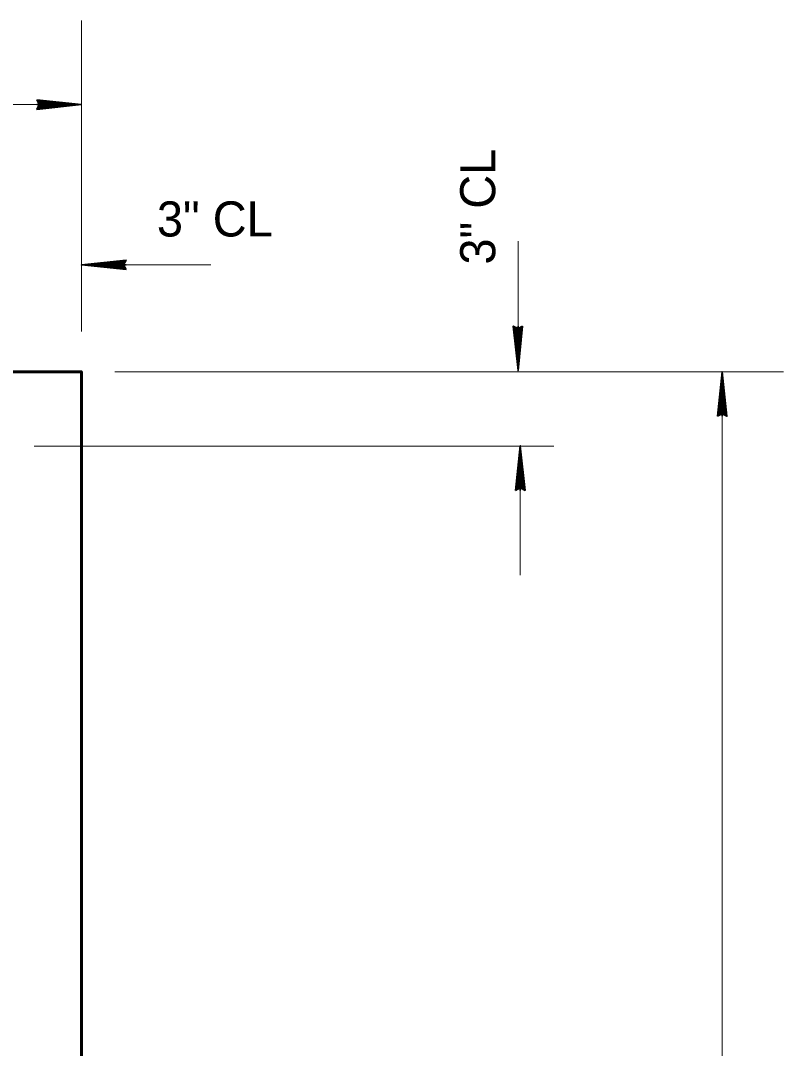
# Model space of a CAD drawing. Extents: x 4.49 to 7.69, y 0.28 to 2.27.
# Drawn here: x 6.09 to 6.2711, y 0.8575 to 1.1015 of the extents above; entities that cross this region are included whole.
import ezdxf

# ---------------------------------------------------------------- set-up
doc = ezdxf.new("R2010")
doc.units = 0
doc.header["$LTSCALE"] = 0.0033
doc.layers.add('1', color=7, linetype='Continuous', lineweight=35)

msp = doc.modelspace()

# ---------------------------------------------------------------- linework, layer by layer
at = {"layer": '1', "lineweight": 13}
for p, q in [((6.104417, 1.027667), (6.104417, 1.1015)), ((5.938, 1.081583), (6.104417, 1.081583)), ((6.208083, 1.028333), (6.208083, 1.049167)), ((6.114333, 1.0435), (6.135167, 1.0435)), ((6.112333, 1.018167), (6.271083, 1.018167)), ((6.2565, 0.602333), (6.2565, 1.018083)), ((6.104417, 0.933083), (6.104417, 1.005917)), ((6.093167, 1.0005), (6.216583, 1.0005)), ((6.208583, 0.969833), (6.208583, 0.990667))]:
    msp.add_line(p, q, dxfattribs=at)
at = {"layer": '1'}
for p, q in [((6.093833, 1.081583), (6.104417, 1.081583)), ((6.094, 1.080917), (6.101333, 1.081667)), ((6.094083, 1.082583), (6.101917, 1.081667)), ((6.094083, 1.082583), (6.101917, 1.081667)), ((6.094083, 1.0825), (6.101917, 1.081667)), ((6.094083, 1.082417), (6.101917, 1.081583)), ((6.094083, 1.082417), (6.101917, 1.081417)), ((6.094083, 1.08075), (6.101417, 1.081583)), ((6.094083, 1.080667), (6.101417, 1.081417)), ((6.094083, 1.0805), (6.101417, 1.081333)), ((6.11475, 1.044583), (6.107417, 1.04375)), ((6.11475, 1.044417), (6.107417, 1.043667)), ((6.11475, 1.044333), (6.107417, 1.0435)), ((6.114833, 1.044167), (6.1075, 1.043417)), ((6.115, 1.0435), (6.104417, 1.0435)), ((6.11475, 1.042667), (6.106917, 1.043667)), ((6.11475, 1.042667), (6.106917, 1.0435)), ((6.11475, 1.0425), (6.106917, 1.043417)), ((6.11475, 1.0425), (6.106917, 1.043417)), ((6.11475, 1.042583), (6.106917, 1.043417)), ((6.207, 1.02875), (6.207833, 1.021417)), ((6.207167, 1.02875), (6.207917, 1.021417)), ((6.20725, 1.02875), (6.208083, 1.021417)), ((6.207417, 1.028833), (6.208167, 1.0215)), ((6.208917, 1.02875), (6.207917, 1.020917)), ((6.208083, 1.029), (6.208083, 1.018417)), ((6.208917, 1.02875), (6.208083, 1.020917)), ((6.209083, 1.02875), (6.208167, 1.020917)), ((6.209083, 1.02875), (6.208167, 1.020917)), ((6.209, 1.02875), (6.208167, 1.020917)), ((6.2565, 1.007583), (6.2565, 1.018167)), ((6.2555, 1.007833), (6.256417, 1.015667)), ((6.2555, 1.007833), (6.256417, 1.015667)), ((6.255583, 1.007833), (6.256417, 1.015667)), ((6.255667, 1.007833), (6.2565, 1.015667)), ((6.255667, 1.007833), (6.256667, 1.015667)), ((6.257167, 1.00775), (6.256417, 1.015083)), ((6.257333, 1.007833), (6.2565, 1.015167)), ((6.257417, 1.007833), (6.256667, 1.015167)), ((6.257583, 1.007833), (6.25675, 1.015167)), ((6.208583, 0.99), (6.208583, 1.000583)), ((6.207583, 0.99025), (6.2085, 0.998083)), ((6.207583, 0.99025), (6.2085, 0.998083)), ((6.207667, 0.99025), (6.2085, 0.998083)), ((6.20775, 0.99025), (6.208583, 0.998083)), ((6.20775, 0.99025), (6.20875, 0.998083)), ((6.20925, 0.990167), (6.2085, 0.9975)), ((6.209417, 0.99025), (6.208583, 0.997583)), ((6.2095, 0.99025), (6.20875, 0.997583)), ((6.209667, 0.99025), (6.208833, 0.997583))]:
    msp.add_line(p, q, dxfattribs=at)
for points in [[(6.093833, 1.082667), (6.104417, 1.081583), (6.093833, 1.080417), (6.094417, 1.081583)], [(6.094583, 1.081667), (6.09925, 1.08175), (6.09925, 1.081667), (6.098333, 1.081667), (6.094583, 1.08175), (6.097583, 1.081833), (6.094417, 1.081917), (6.096667, 1.082), (6.094417, 1.082083), (6.097917, 1.081833), (6.102583, 1.081667), (6.101667, 1.081417), (6.102917, 1.081417), (6.094583, 1.081417), (6.097, 1.08125), (6.094417, 1.08125), (6.09975, 1.081667), (6.094417, 1.081)], [(6.115, 1.042417), (6.104417, 1.0435), (6.115, 1.044667), (6.114417, 1.0435)], [(6.11425, 1.043417), (6.109583, 1.043333), (6.109583, 1.043417), (6.1105, 1.043417), (6.11425, 1.043333), (6.11125, 1.04325), (6.114417, 1.043167), (6.112167, 1.043083), (6.114417, 1.043), (6.110917, 1.04325), (6.10625, 1.043417), (6.107167, 1.043667), (6.105917, 1.043667), (6.11425, 1.043667), (6.111833, 1.043833), (6.114417, 1.043833), (6.109083, 1.043417), (6.114417, 1.044083)], [(6.209167, 1.029), (6.208083, 1.018417), (6.206917, 1.029), (6.208083, 1.028417)], [(6.208167, 1.02825), (6.20825, 1.023583), (6.208167, 1.023583), (6.208167, 1.0245), (6.20825, 1.02825), (6.208333, 1.02525), (6.208417, 1.028417), (6.2085, 1.026167), (6.208583, 1.028417), (6.208333, 1.024917), (6.208167, 1.02025), (6.207917, 1.021167), (6.207917, 1.019917), (6.207917, 1.02825), (6.20775, 1.025833), (6.20775, 1.028417), (6.208167, 1.023083), (6.2075, 1.028417)], [(6.255417, 1.007583), (6.2565, 1.018167), (6.257667, 1.007583), (6.2565, 1.008167)], [(6.256417, 1.008333), (6.256333, 1.013), (6.256417, 1.013), (6.256417, 1.012083), (6.256333, 1.008333), (6.25625, 1.011333), (6.256167, 1.008167), (6.256083, 1.010417), (6.256, 1.008167), (6.25625, 1.011667), (6.256417, 1.016333), (6.256667, 1.015417), (6.256667, 1.016667), (6.256667, 1.008333), (6.256833, 1.01075), (6.256833, 1.008167), (6.256417, 1.0135), (6.257083, 1.008167)], [(6.2075, 0.99), (6.208583, 1.000583), (6.20975, 0.99), (6.208583, 0.990583)], [(6.2085, 0.99075), (6.208417, 0.995417), (6.2085, 0.995417), (6.2085, 0.9945), (6.208417, 0.99075), (6.208333, 0.99375), (6.20825, 0.990583), (6.208167, 0.992833), (6.208083, 0.990583), (6.208333, 0.994083), (6.2085, 0.99875), (6.20875, 0.997833), (6.20875, 0.999083), (6.20875, 0.99075), (6.208917, 0.993167), (6.208917, 0.990583), (6.2085, 0.995917), (6.209167, 0.990583)]]:
    msp.add_lwpolyline(points, close=True, dxfattribs=at)
for points in [[(6.094583, 1.081667), (6.094167, 1.082417), (6.094417, 1.082167), (6.094583, 1.081833), (6.094833, 1.081917), (6.094667, 1.08225), (6.0945, 1.0815), (6.094333, 1.081), (6.094083, 1.080583)], [(6.11425, 1.043417), (6.114667, 1.042667), (6.114417, 1.042917), (6.11425, 1.04325), (6.114, 1.043167), (6.114167, 1.042833), (6.114333, 1.043583), (6.1145, 1.044083), (6.11475, 1.0445)], [(6.208167, 1.02825), (6.208917, 1.028667), (6.208667, 1.028417), (6.208333, 1.02825), (6.208417, 1.028), (6.20875, 1.028167), (6.208, 1.028333), (6.2075, 1.0285), (6.207083, 1.02875)], [(6.256417, 1.008333), (6.255667, 1.007917), (6.255917, 1.008167), (6.25625, 1.008333), (6.256167, 1.008583), (6.255833, 1.008417), (6.256583, 1.00825), (6.257083, 1.008083), (6.2575, 1.007833)], [(6.2085, 0.99075), (6.20775, 0.990333), (6.208, 0.990583), (6.208333, 0.99075), (6.20825, 0.991), (6.207917, 0.990833), (6.208667, 0.990667), (6.209167, 0.9905), (6.209583, 0.99025)]]:
    msp.add_lwpolyline(points, dxfattribs=at)
at = {"layer": '1', "lineweight": 60}
msp.add_lwpolyline([(5.854417, 0.684833), (5.93775, 0.684833), (5.93775, 1.018167), (6.104417, 1.018167), (6.104417, 0.684833), (6.18775, 0.684833)], dxfattribs=at)

# ---------------------------------------------------------------- texts
at = {"layer": '1'}
msp.add_text('3" CL', height=0.008334, rotation=90, dxfattribs=at).set_placement((6.202667, 1.043583))
msp.add_text('3" CL', height=0.008334, dxfattribs=at).set_placement((6.122333, 1.05025))

doc.saveas('drawing.dxf')
